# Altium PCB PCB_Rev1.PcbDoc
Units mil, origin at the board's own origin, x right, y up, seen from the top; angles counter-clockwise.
Board outline 802 x 1535 mil, 4 copper layers (Top Layer, Signal Layer 1, Internal Plane 1(GND), Bottom Layer), stack 30.634 mil thick; 54 components, 46 nets, 254 pads, 102 vias.
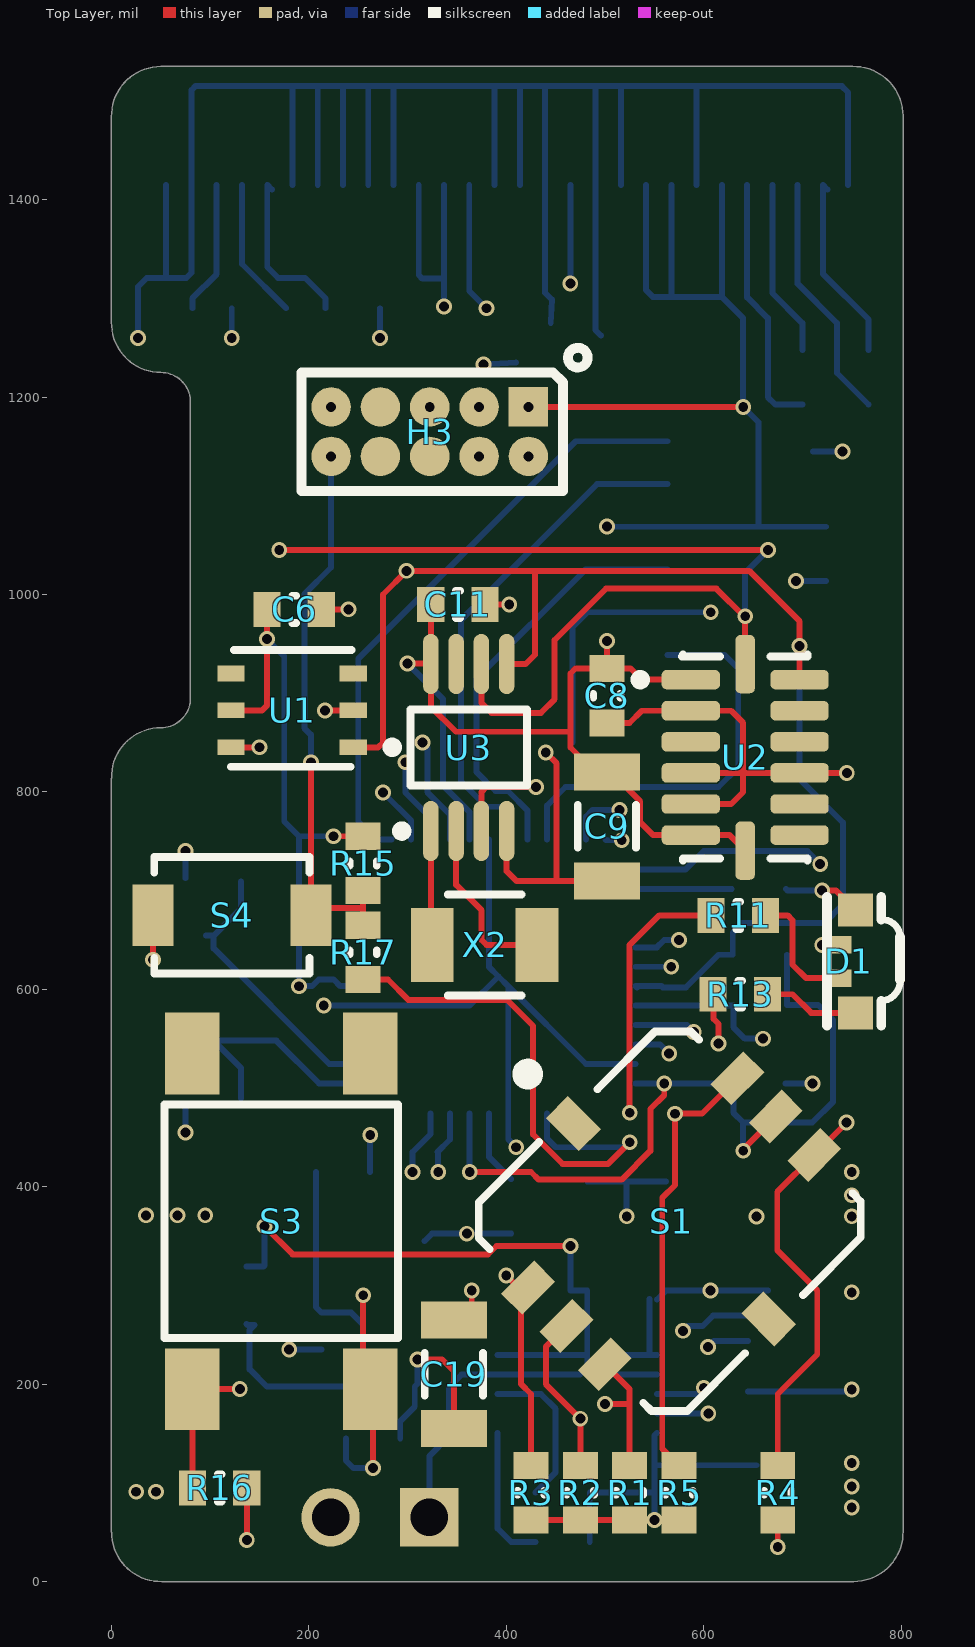
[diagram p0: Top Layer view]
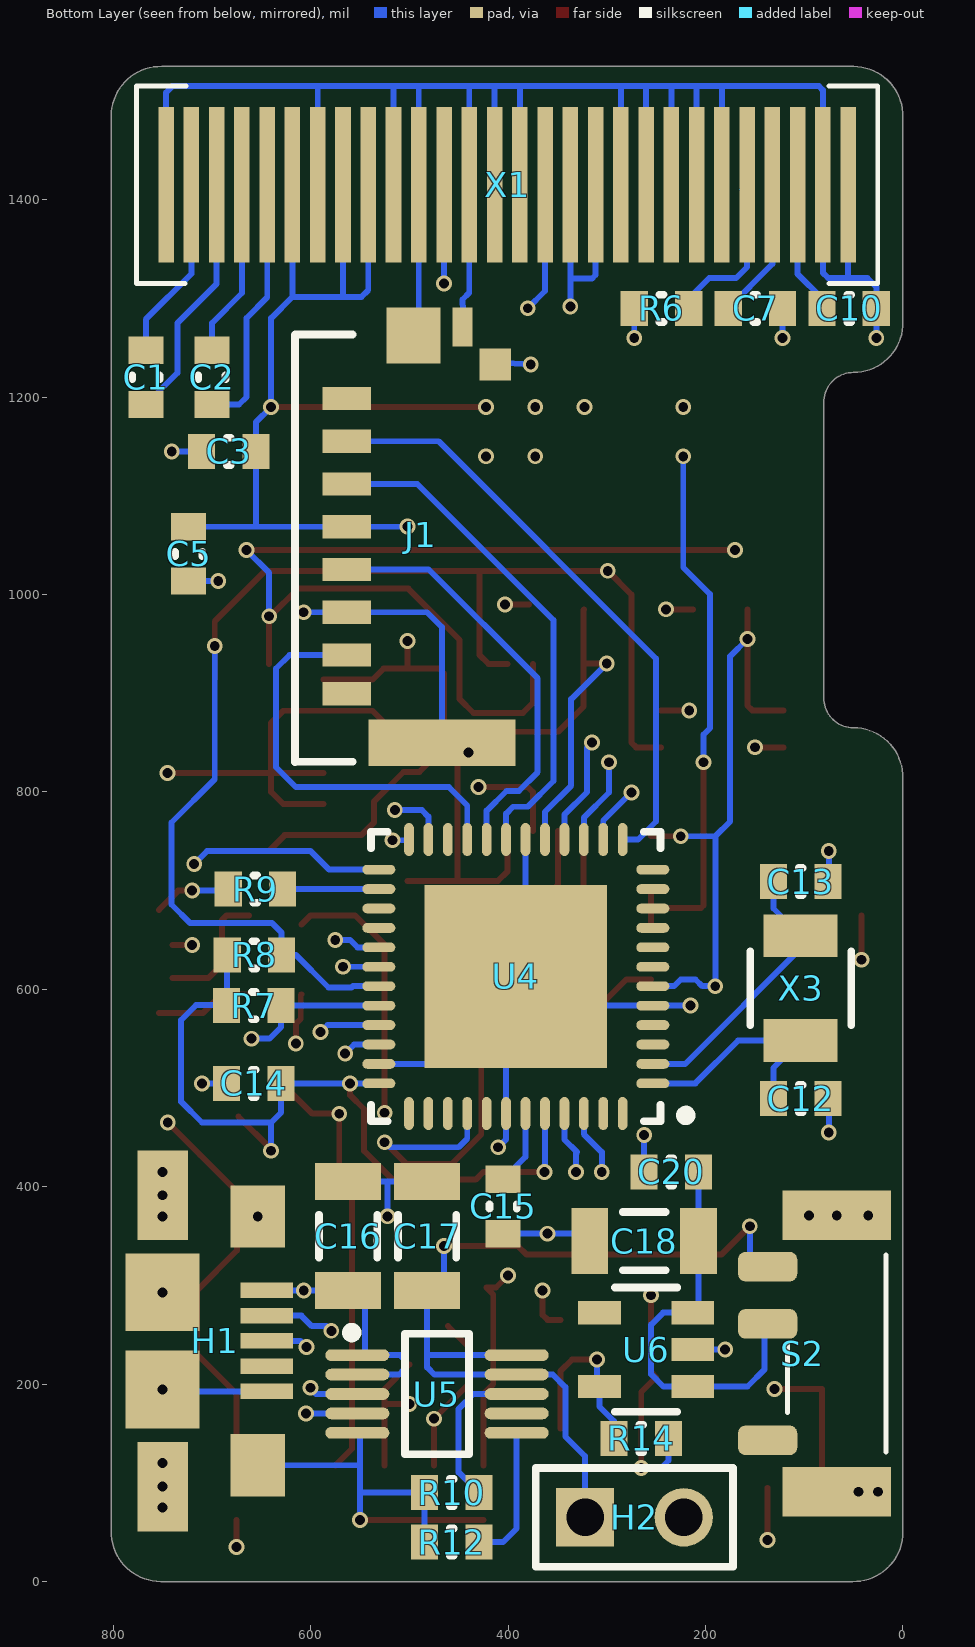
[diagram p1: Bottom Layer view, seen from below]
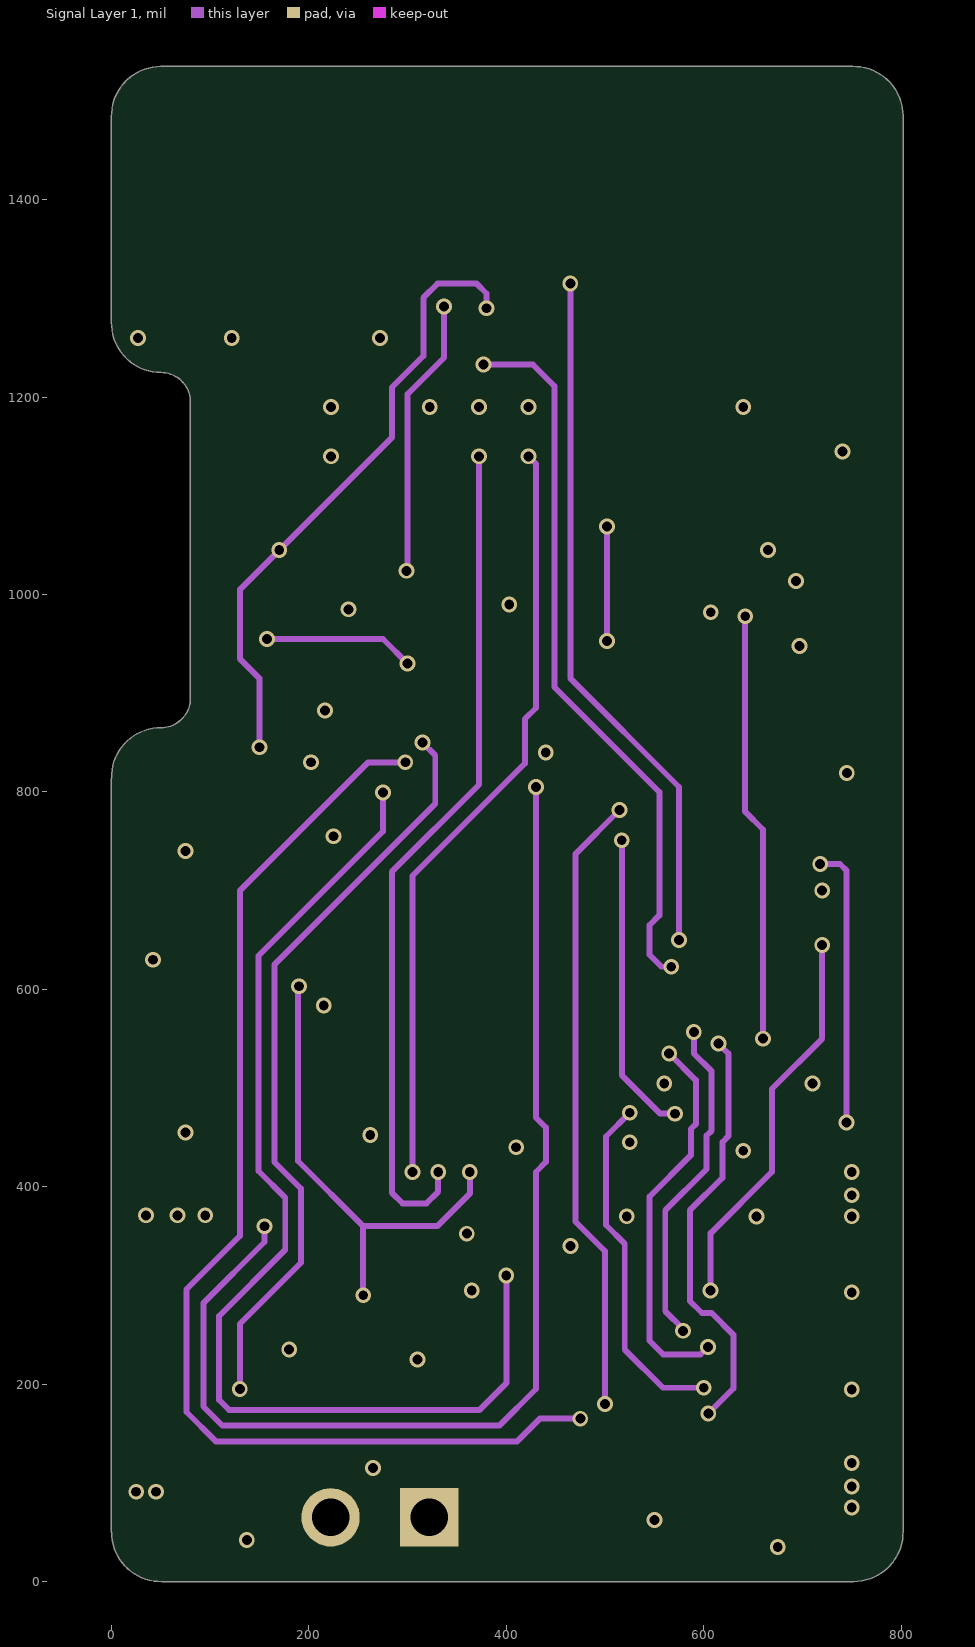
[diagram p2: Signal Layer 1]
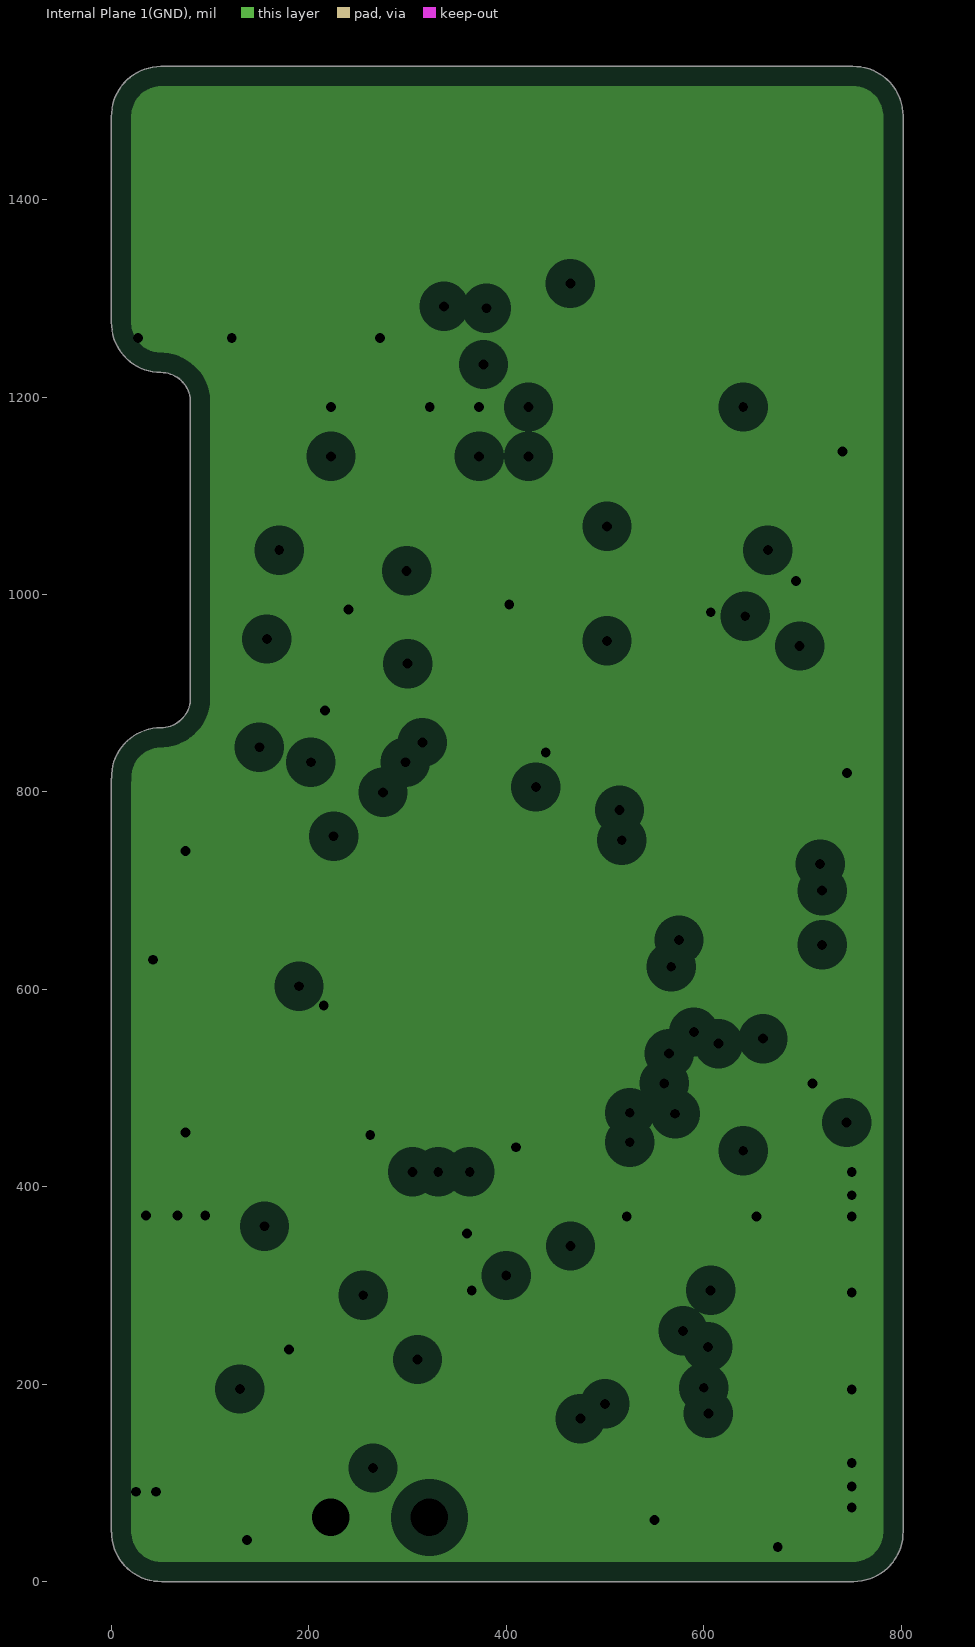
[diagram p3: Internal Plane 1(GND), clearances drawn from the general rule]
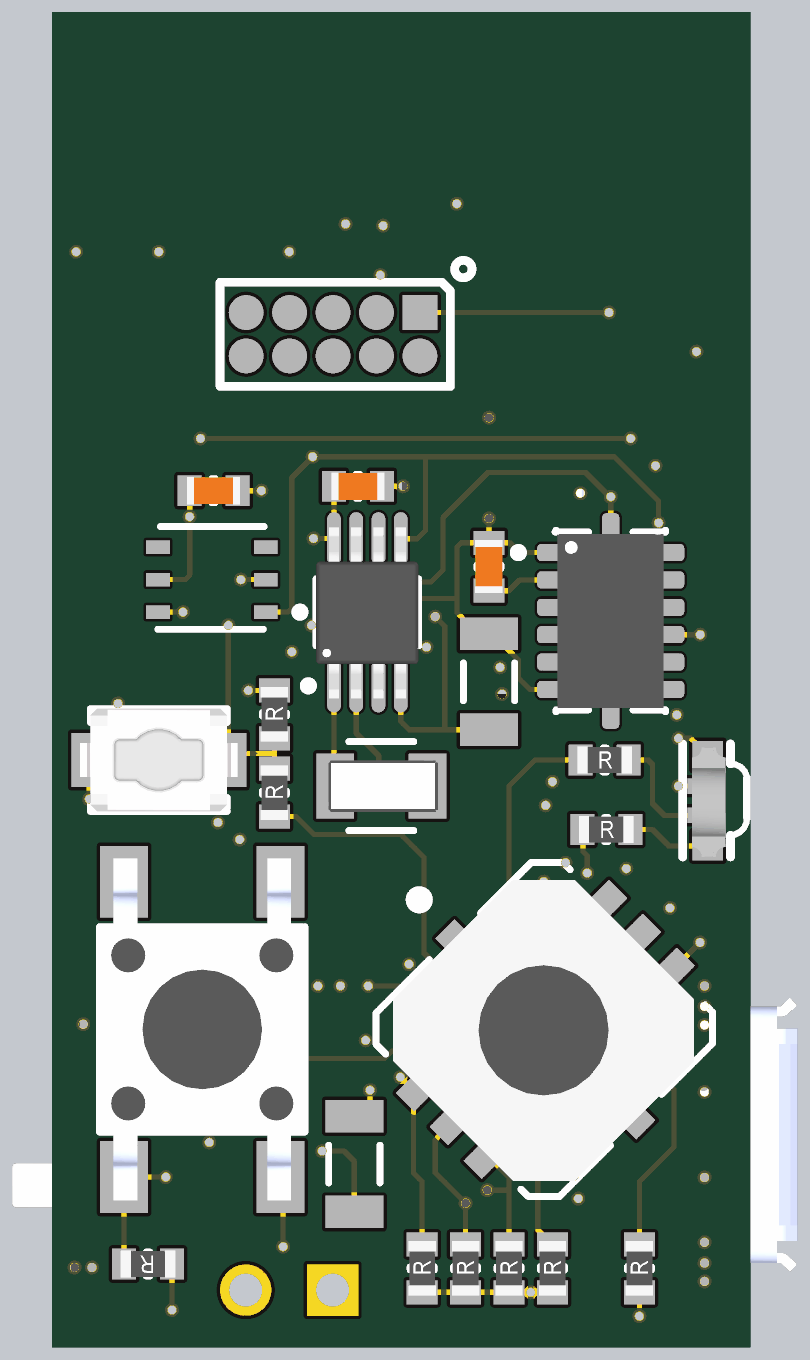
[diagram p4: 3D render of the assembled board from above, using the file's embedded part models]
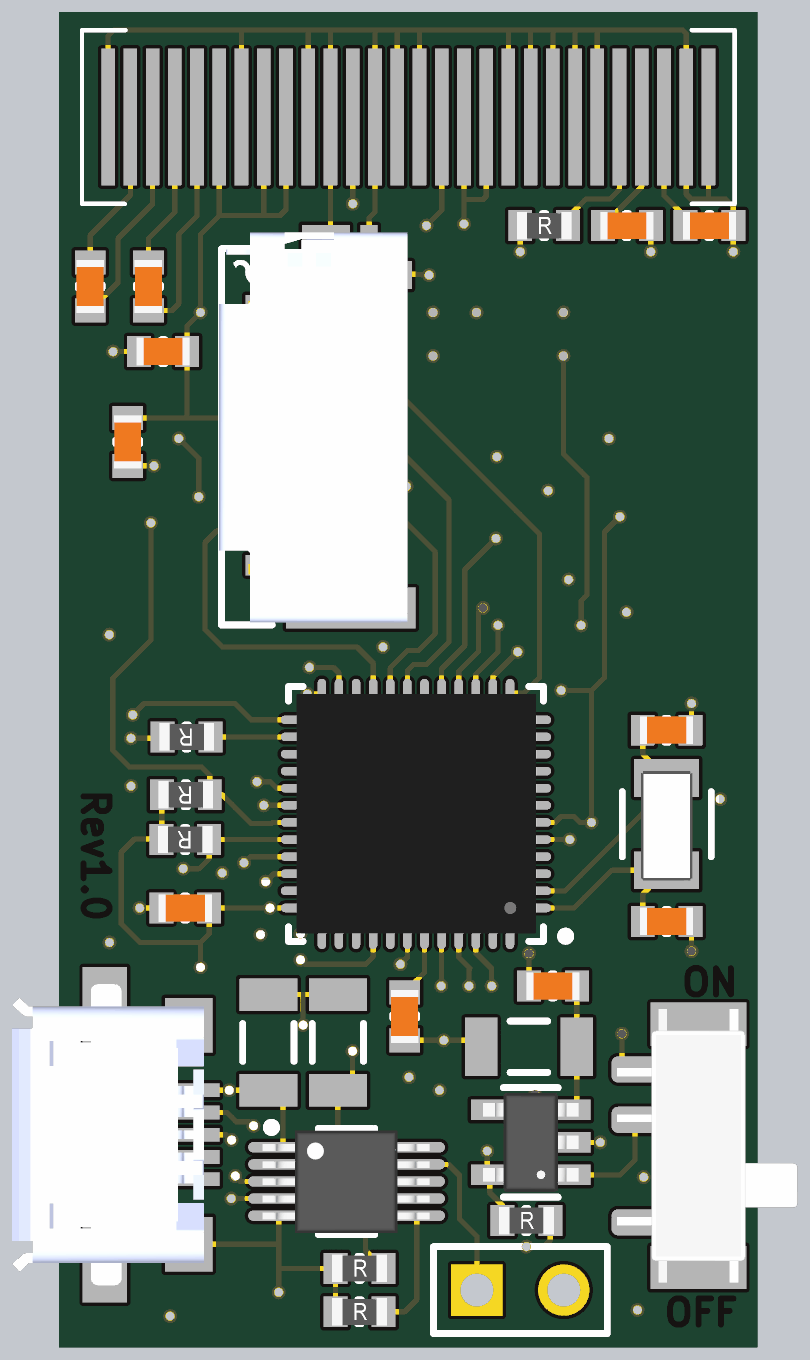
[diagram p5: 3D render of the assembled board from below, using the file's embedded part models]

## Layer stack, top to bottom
Top Solder: solder mask 0.4, Solder Resist, Dk 3.5
Top Layer: signal copper 1.4
Dielectric 1: core 10, FR-4, Dk 4.2
Signal Layer 1: signal copper 1.417
Dielectric 4: prepreg 5, Dk 4.2
Internal Plane 1(GND): plane copper 1.417, net GND
Dielectric 3: core 10, Dk 4.2
Bottom Layer: signal copper 1.4
Bottom Solder: solder mask 0.4, Solder Resist, Dk 3.5

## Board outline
-0.03,49.99 -0.03,814.03 0.01,814.03 cw(c50,815) 50,865 ccw(c50,895) 79.99,895.58 80,895.58 80,1194.42 79.99,1194.42 ccw(c50,1195) 50,1225 49.96,1225.03 cw(c49.96,1275.03) -0.03,1276 -0.03,1484 cw(c49.96,1484.97) 49.96,1534.97 49.96,1535 750.97,1535 cw(c751.94,1485.01) 801.94,1485.01 801.97,1485.01 801.97,51 cw(c751.98,50.03) 751.98,0.03 751.98,0 50.97,0 cw(c50,49.99)

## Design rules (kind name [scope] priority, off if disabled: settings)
Clearance Clearance_J1 [All vs HasFootprint ('0473092851')] p1: gap=7.5
Clearance Clearance_D1 [All vs HasFootprint ('HSMF-C115')] p2: gap=9.5
Clearance Clearance_U5 [All vs HasFootprint ('TSSOP50P490X110-10N')] p3: gap=7.8
Clearance Clearance_H1 [All vs HasFootprint ('1981584-1')] p4: gap=9.5
Clearance Clearance_U3 [All vs HasFootprint ('TSOP65P490X110-8N')] p5: gap=9.5
Clearance Clearance_U4 [HasFootprint ('QFN48')] p6: gap=9.5
Clearance Clearance_X1 [HasFootprint ('OLED_GLASS 0.66 INCH')] p7: gap=9.5
Clearance [All] p8: gap=10
MinimumSolderMaskSliver [All] p1: minsoldermaskwidth=2
PlaneClearance [All] p1: clearance=20
PlaneConnect PlaneConnect_Via [(IsVia)] p1: planeconnectstyle=Direct reliefexpansion=20 reliefentries=4 reliefconductorwidth=10 reliefairgap=10
PlaneConnect [All] p2: planeconnectstyle=Relief reliefexpansion=20 reliefentries=4 reliefconductorwidth=10 reliefairgap=10
PolygonConnect [All] p1: connectstyle=Relief reliefconductorwidth=10 reliefentries=4 polygonreliefangle="90 Angle" airgapwidth=10
RoutingVias [All] p1: holewidth=10 width=16 viastyle="Through Hole" minholewidth=10 minwidth=16 maxholewidth=20 maxwidth=50
SilkToSilkClearance [All] p1: silktosilkclearance=5
SilkToSolderMaskClearance [IsPad] p1: minsilkscreentomaskgap=3 clearancetoexposedcopper=TRUE
SolderMaskExpansion [All] p1: expansion=4
Width [All] p1: maxlimit=10 minlimit=6 preferedwidth=6
25 further rules are at their usual default settings.

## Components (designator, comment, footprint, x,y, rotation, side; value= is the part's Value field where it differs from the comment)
C1 "1uF" CAPC1608X09L 767,1220 r90 bottom
C2 "1uF" CAPC1608X09L 700,1220 r90 bottom
C3 "1uF" CAPC1608X09L 683,1145 r180 bottom
C5 "0.1uF" CAPC1608X09L 723.68,1041.12 r90 bottom
C6 "0.1uF" CAPC1608X09L 185,985 r180 top
C7 "4.7uF" CAPC1608X09L 149.41,1290 r0 bottom
C8 "0.1uF" CAPC1608X09L 501.97,897.44 r90 top
C9 "10uF" CAPC3216X160L 501.97,765 r270 top
C10 "2.2uF" CAPC1608X09L 54.41,1290 r0 bottom
C11 "0.1uF" CAPC1608X09L 351,990 r180 top
C12 "22pF" CAPC1608X09L 103.52,489.22 r180 bottom
C13 "22pF" CAPC1608X09L 103.52,709.22 r180 bottom
C14 "0.1uF" CAPC1608X09L 657.56,504.73 r0 bottom
C15 "1uF" CAPC1608X09L 405,380 r90 bottom
C16 "4.7uF" CAPC3216X160L 561.97,350 r90 bottom
C17 "4.7uF" CAPC3216X160L 481.97,350 r90 bottom
C18 "4.7uF" CAPC3216X160L 262.09,345 r0 bottom
C19 "4.7uF" CAPC3216X160L 346.97,210 r90 top
C20 "0.1uF" CAPC1608X09L 234.53,415 r0 bottom
D1 "RGB" HSMF-C115 753.78,680.45 r270 top
H1 "Micro USB" 1981584-1 697.31,243.79 r270 bottom
H2 "CON2" HDR1X2-EMPTY 271.97,65 r180 bottom
H3 "CON5X2-50MIL" HDR5X2-50MIL-SMT 322.44,1165 r180 top
J1 "0473092851" 0473092851 563.49,1047.03 r90 bottom locked
R1 "10K" RESC1608X06L 525,90 r90 top
R2 "10K" RESC1608X06L 475,90 r90 top
R3 "10K" RESC1608X06L 425,90 r90 top
R4 "10K" RESC1608X06L 675,90 r90 top
R5 "10K" RESC1608X06L 575,90 r90 top
R6 "390K" RESC1608X06L 244.53,1290 r180 bottom
R7 "10K" RESC1608X06L 657.56,583.47 r0 bottom
R8 "10K" RESC1608X06L 656.97,635 r0 bottom
R9 "470R" RESC1608X06L 655.98,701.58 r0 bottom
R10 "10K" RESC1608X06L 456.97,90 r180 bottom
R11 "470R" RESC1608X06L 635,675 r0 top
R12 "1K" RESC1608X06L 457,40 r180 bottom
R13 "470R" RESC1608X06L 636.97,595 r0 top
R14 "0R" RESC1608X06L 265,145 r180 bottom
R15 "10K" RESC1608X06L 255,727.56 r90 top
R16 "10K" RESC1608X06L 109.56,95 r180 top
R17 "330R" RESC1608X06L 255,637.44 r90 top
S1 "Navigation Switch" "NAVIGATION - DX" 566.97,365 r0 top
S2 "" SLIDE_SWITCH_DX 66.97,231 r90 bottom
S3 "Tactile_Switch" FSM6JSMA 171.97,365 r180 top
S4 "Push" TL1015AF160QG 121.97,675 r0 top
U1 "HDC1080DMBT" S-PWSON-N6 245,845.2 r180 top
U2 "ADXL345BCCZ-RL7" LGA80P300X500X100-14N 641.97,835 r0 top
U3 "DS1340U-33+" TSOP65P490X110-8N 361.97,845 r90 top
U4 "ATSAMD21G18A-MU" QFN48 392.11,613 r0 bottom
U5 "MCP73833-FCI/UN" TSSOP50P490X110-10N 471.97,190 r180 bottom
U6 "LP2985-33DBVR" SOT95P280X144-5N 260,235 r0 bottom
X1 "OLED_GLASS 0.66 inch" "OLED_GLASS 0.66 INCH" 400.87,1415 r180 top
X2 "ECS-.327-12.5-34B" ECS-.327-12.5-34B 380,645 r180 top
X3 "ECS-.327-12.5-34B" ECS-.327-12.5-34B 103.52,599.22 r90 bottom

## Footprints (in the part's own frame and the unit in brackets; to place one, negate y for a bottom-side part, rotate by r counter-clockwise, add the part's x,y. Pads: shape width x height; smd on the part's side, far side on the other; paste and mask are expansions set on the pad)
1981584-1 [mm] "CONN RCPT MICRO USB TYPE AB"
  rect 0.4x1.35 smd: 1(-1.3,1.338) 2(-0.65,1.338) 3(0,1.338) 4(0.65,1.338) 5(1.3,1.338)
  rect 2.3x1.3 smd: 6(-3.75,-1.337) 6(3.75,-1.337)
  rect 1.6x1.4 smd: 6(-3.2,1.113) 6(3.2,1.113)
  rect 2x1.9 smd: 6(-1.25,-1.337) 6(1.25,-1.337)
  body extent -4.4,-4.05 4.4,1.55, height 2.75
0473092851 [mm] "CONN MICRO SD CARD PUSH-PULL R/A"
  rect 0.6x1.25 smd: 1(3.85,0) 2(2.75,0) 3(1.65,0) 4(0.55,0) 5(-0.55,0) 6(-1.65,0) 7(-2.75,0) 8(-3.75,0)
  rect 1.2x3.79 smd: G1(-5.004,-2.451)
  rect 1.45x1.4 smd: G2(5.472,-1.719)
  rect 1x0.508 smd: G3(5.687,-2.982)
  rect 0.813x0.813 smd: G4(4.725,-3.825)
  silkscreen extent -5.51,-0.15 5.5,1.33, body extent -5.43,-4.1 5.97,1.4, height 2.88
CAPC1608X09L [mm] "Chip Capacitor, 2-Leads, Body 1.6x0.8mm, IPC High Density (0603 dense)"
  rect 0.7x0.9 smd: 1(-0.7,0) 2(0.7,0)
  silkscreen extent -0.05,-0.35 0.05,0.35, body extent -0.89,-0.48 0.88,0.48, height 1.03
CAPC3216X160L [mm] "Chip Capacitor, 2-Leads, Body 3.2x1.6mm, IPC Least Density(C1206)"
  rect 0.95x1.7 smd: 1(-1.4,0) 2(1.4,0)
  silkscreen extent -0.55,-0.75 0.55,0.75, body extent -1.7,-0.9 1.7,0.9, height 1.9
ECS-.327-12.5-34B [mm] "SMT Crystal, 2-Leads, Body 3.2x1.5mm, IPC Medium Density"
  rect 1.1x1.9 smd: 1(-1.3,0) 2(1.4,0)
  silkscreen extent -0.9,-1.3 1,1.3, body extent -1.6,-0.75 1.6,0.75, height 0.91
FSM6JSMA [mil] "SWITCH TACTILE SPST-NO 0.05A 12V"
  rect 55.12x82.68 smd: 1(90,170) 2(90,-170) 3(-90,170) 4(-90,-170)
  silkscreen extent -118,-118 118,118, body extent -118,-197 118,197, height 276
HDR1X2-EMPTY [mm]
  rect 1.5x1.5 hole 0.965: 1(-1.27,0)
  round 1.5 hole 0.965: 2(1.27,0)
  silkscreen extent -2.54,-1.27 2.54,1.27
HDR5X2-50MIL-SMT [mil]
  rect 40x40 smd: 1(-100,-25)
  round 40 smd: 2(-100,25) 3(-50,-25) 4(-50,25) 5(0,-25) 6(0,25) 7(50,-25) 8(50,25) 9(100,-25) 10(100,25)
  silkscreen extent -160,-85 130,60
HSMF-C115 [mm] "Led RGB 10mA SMD R/A RoHS"
  rect 0.85x0.9 smd: 1(0,0) 4(2.65,0)
  rect 0.45x0.5 smd: 2(0.9,-0.35) 3(1.757,-0.35)
  silkscreen extent -0.33,-0.74 2.97,1.15, body extent -0.23,-0.47 2.97,0.52, height 1.4
LGA80P300X500X100-14N [mm] "LGA, 14-Pins, Body 3.2x5.2mm (max), Pitch 0.80mm, IPC Medium Density"
  rrect50% 1.5x0.5 smd mask+0.076: 1(-1.399,2) 2(-1.399,1.2) 3(-1.399,0.4) 4(-1.399,-0.4) 5(-1.399,-1.2) 6(-1.399,-2) 8(1.401,-2) 9(1.401,-1.2) 10(1.401,-0.4) 11(1.401,0.4) 12(1.401,1.2) 13(1.401,2)
  rrect50% 0.5x1.5 smd mask+0.076: 7(0.001,-2.4) 14(0.001,2.4)
  silkscreen extent -2.82,-2.65 1.6,2.65, body extent -1.55,-2.55 1.55,2.55, height 1
"NAVIGATION - DX" [mm] "Navigation Switch - DX"
  rect 1.2x0.762 smd rot 45: 1(-3.682,-1.706) 2(-2.694,-2.694) 3(-1.706,-3.682) 4(3.682,1.706) 5(2.694,2.694) 6(1.706,3.682)
  rect 0.8x1.2 smd rot 45: ""(-2.514,2.514) ""(2.514,-2.514)
  silkscreen extent -4.95,-4.88 4.88,4.88, body extent -5.35,-5.33 5.24,5.27, height 4.32
"OLED_GLASS 0.66 INCH" [mm] "OLED_GLASS 0.66 INCH"
  rect 0.4x4 smd far side: 1(-8.775,0) 2(-8.125,0) 3(-7.475,0) 4(-6.825,0) 5(-6.175,0) 6(-5.525,0) 7(-4.875,0) 8(-4.225,0) 9(-3.575,0) 10(-2.925,0) 11(-2.275,0) 12(-1.625,0) 13(-0.975,0) 14(-0.325,0) 15(0.325,0) 16(0.975,0) 17(1.625,0) 18(2.275,0) 19(2.925,0) 20(3.575,0) 21(4.225,0) 22(4.875,0) 23(5.525,0) 24(6.175,0) 25(6.825,0) 26(7.475,0) 27(8.125,0) 28(8.775,0)
QFN48 [mm] "QFN, 48-Leads, Body 7x7mm, Pitch 0.5mm, IPC Medium Density"
  oval 0.85x0.25 smd: 1(-3.525,2.75) 2(-3.525,2.25) 3(-3.525,1.75) 4(-3.525,1.25) 5(-3.525,0.75) 6(-3.525,0.25) 7(-3.525,-0.25) 8(-3.525,-0.75) 9(-3.525,-1.25) 10(-3.525,-1.75) 11(-3.525,-2.25) 12(-3.525,-2.75) 25(3.525,-2.75) 26(3.525,-2.25) 27(3.525,-1.75) 28(3.525,-1.25) 29(3.525,-0.75) 30(3.525,-0.25) 31(3.525,0.25) 32(3.525,0.75) 33(3.525,1.25) 34(3.525,1.75) 35(3.525,2.25) 36(3.525,2.75)
  oval 0.25x0.85 smd: 13(-2.75,-3.525) 14(-2.25,-3.525) 15(-1.75,-3.525) 16(-1.25,-3.525) 17(-0.75,-3.525) 18(-0.25,-3.525) 19(0.25,-3.525) 20(0.75,-3.525) 21(1.25,-3.525) 22(1.75,-3.525) 23(2.25,-3.525) 24(2.75,-3.525) 37(2.75,3.525) 38(2.25,3.525) 39(1.75,3.525) 40(1.25,3.525) 41(0.75,3.525) 42(0.25,3.525) 43(-0.25,3.525) 44(-0.75,3.525) 45(-1.25,3.525) 46(-1.75,3.525) 47(-2.25,3.525) 48(-2.75,3.525)
  rect 4.7x4.7 smd paste-0.5: 49(0,0)
  silkscreen extent -4.5,-3.72 3.72,3.72, body extent -3.52,-3.51 3.5,3.51, height 0.78
RESC1608X06L [mm] "Chip Resistor, 2-Leads, Body 1.6x0.8mm, IPC High Density (0603 dense)"
  rect 0.7x0.9 smd: 1(-0.7,0) 2(0.7,0)
  silkscreen extent -0.05,-0.35 0.05,0.35, body extent -0.85,-0.47 0.85,0.47, height 0.6
S-PWSON-N6 [mm] "DMB (S-PWSON-N6)"
  rect 0.7x0.4 smd mask+0.076: 1(0,0) 2(0,-0.95) 3(0,-1.9) 5(3.15,-0.95) 6(3.15,0)
  rect 0.7x0.4 smd paste+0 mask+0.076: 4(3.15,-1.9)
  silkscreen extent -1.13,-2.5 3.15,0.5, body extent 0,-2.57 3.15,0.58, height 0.8
SLIDE_SWITCH_DX [mil] "Slide Switch DX"
  rrect50% 30x60 smd: 1(88,70) 2(30,70) 3(-88,70)
  rect 50x110 smd: 4(-140,0) 5(140,0)
  silkscreen extent -100,-50 100,50, body extent -157,-114 158,94, height 60
SOT95P280X144-5N [mm] "SOT23, 5-Leads, Body 3.1x3.0mm (max), Pitch 0.95mm, IPC Medium Density (RFMD SOT23-5)"
  rect 1.1x0.6 smd: 1(-1.2,0.95) 2(-1.2,0) 3(-1.2,-0.95) 4(1.2,-0.95) 5(1.2,0.95)
  silkscreen extent -0.8,-1.6 0.8,1.6, body extent -1.4,-1.45 1.4,1.45, height 1.45
TL1015AF160QG [mm] "SWITCH TACTILE SPST-NO 0.05A 12V"
  rect 1.05x1.59 smd: 1(-2.032,0) 2(2.032,0)
  silkscreen extent -2,-1.5 2,1.5, body extent -2.3,-1.5 2.3,1.5, height 2
TSOP65P490X110-8N [mm] "TSOP, 8-Leads, Body 3.0x3.0mm (max), Pitch 0.65mm, IPC Medium Density"
  oval 1.55x0.4 smd mask+0.076: 1(-2.15,0.975) 2(-2.15,0.325) 3(-2.15,-0.325) 4(-2.15,-0.975) 5(2.15,-0.975) 6(2.15,-0.325) 7(2.15,0.325) 8(2.15,0.975)
  silkscreen extent -2.27,-1.5 0.97,1.85, body extent -2.51,-1.5 2.49,1.5, height 1.1
TSSOP50P490X110-10N [mm] "TSSOP, 10-Leads, Body 3.1x3.1mm (max), Pitch 0.50mm, IPC Medium Density(10MSOP)"
  oval 1.65x0.3 smd: 1(-2.05,1) 2(-2.05,0.5) 3(-2.05,0) 4(-2.05,-0.5) 5(-2.05,-1) 6(2.05,-1) 7(2.05,-0.5) 8(2.05,0) 9(2.05,0.5) 10(2.05,1)
  silkscreen extent -2.32,-1.55 0.82,1.7, body extent -2.45,-1.51 2.43,1.49, height 1.04

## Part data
C1 C2 C3 C15: library part CAP_0603, "CAP, 1uF, 0603"
C5 C6 C8 C11 C14 C20: library part CAP_0603, "CAP, 0.1uF, 0603"
C7: library part CAP_0603, "CAP, 4.7uF, 0603"
C9: library part CAP_1206, "CAP, 40uF, 1206"
C10: library part CAP_0603, "CAP, 2.2uF, 0603"
C12 C13: library part CAP_0603, "CAP, 22pF, 0603"
C16 C17 C18 C19: library part CAP_1206, "CAP, 4.7uF, 1206"
D1: library part HSMF-C115, "LED,RGB,10mA,SMD,R/A,RoHS"
H1: library part 1981584-1, "CONN RCPT MICRO USB TYPE AB"
H2: library part CON2-EMPTY_PAD, "EMPTY SOLDER 2POS"
H3: library part CON5X2_50mil, "JTAG CONN HEADER 5X2POS 50mil\" PADS"
J1: "9 (8 + 1) microSD SMT, Right Angle"
R1 R2 R3 R4 R5 R10 R15 R16: library part RES_0603, "RES, 10K, 0603"
R6: library part RES_0603, "RES, 390K, 0603"
R7 R8 R11 R12 R13: library part RES_0603, "RES, 470R, 0603"
R9: library part RES_0603, "RES,470R, 0603"
R14: library part RES_0603, "RES, 0R, 0603"
R17: library part RES_0603, "RES, 330R, 0603"
S1: library part DX_NAV, "DX_Navigation Switch"
S2: library part DX_SLIDE_SWITCH, "DX_SWITCH SLIDE SPDT R/A"
S3: library part FSM6JSMA, "SWITCH TACTILE SPST-NO 0.05A 12V"
S4: library part DX_MINI_TACT_SWITCH, "DX_SWITCH TACTILE"
U1: "Humidity/Temperature Sensor"
U2: "IC ACCEL SPI/I2C 3AX 14LGA"
U3: "IC RTC SERIAL 512K 8-TSSOP"
U4: "IC MCU 32BIT 256KB FLASH 48QFN"
U5: "IC LI-ION/LI-POLY CTRLR 10MSOP"
U6: "IC REG LDO 3.3V .15A SOT23-5"
X1: "0.66 inch OLED_GLASS_Blue"
X2 X3: "CRYSTAL 32.768 KHZ 12.5PF SMD"

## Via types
v1: diameter 16, hole 10, Top Layer to Bottom Layer, tented both sides, 102 vias

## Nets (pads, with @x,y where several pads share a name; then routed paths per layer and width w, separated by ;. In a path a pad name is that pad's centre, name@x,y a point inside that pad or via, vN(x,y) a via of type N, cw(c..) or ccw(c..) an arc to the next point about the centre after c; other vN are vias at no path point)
3.6V_LIPO: C17.1 H2.1 S2.1 U3.3 U5.9 U5.10 | length 2187
  Top Layer w6: v1(155,360) 183.56,331.44 381.44,331.44 390,340 v1(465,340) ; U3.3 374.77,799.77 380,805 v1(430,805)
  Signal Layer 1 w6: v1(155,360) 155,344 93,282 93,177.37 112.37,158 393,158 430,195 430,415 440,425 440,460 430,470 v1(430,805)
  Bottom Layer w6: S2.1 154,319 155,320 v1(155,360) ; H2.1 321.97,126.97 341.9,146.9 341.9,196.9 354.69,209.69 U5.9 474.69,209.69 481.97,216.97 481.97,230 ; U5.10 481.34,229.37 481.97,230 ; v1(465,340) 465,295 465.12,294.88 C17.1 481.97,230
+3.3V: C3.2 C5.2 C6.2 C8.2 C9.1 C11.2 C14.1 H3.1 J1.4 R7.2 R8.2 R14.2 R15.2 S1.5 S3.3 U1.5 U2.1 U2.6 U2.7 U3.8 U4.6 U4.17 U4.36 U4.44 X1.6 X1.8 X1.9 | length 4510.7
  Top Layer w6: U1.5 152.6,882.6 157.44,887.44 v1(157.44,955) C6.2 ; v1(225,755.12) R15.2 ; v1(255,290) 255,211.97 250,206.97 S3.3 265,191.97 v1(265,115) ; v1(300,930) 323.23,930 U3.8 ; C11.2@323,985 323.59,984.41 U3.8 ; v1(363,415) 425,415 432.84,407.16 516.85,407.16 546,436.3 546,444.44 546,478.7 560,492.7 v1(560,504.73) ; v1(422.44,1190) v1(640,1190) ; v1(501.97,953.03) C8.2 ; U2.1 537.26,913.74 526,925 C8.2 ; v1@638.49,436.51 v1(640,436.51) 640,438.03 S1.5 ; U2.7 626.27,756.26 U2.6 548.74,756.26 535.69,769.31 535.69,790.39 505.96,820.12 C9.1 489.88,820.12 465,845 465,861 ; U3.8 323.59,886.41 349,861 465,861 ; 465,861 465,920 470,925 C8.2
  Signal Layer 1 w6: v1(157.44,955) 275,955 v1(300,930) ; v1@190,605 v1(190,603.16) 189,602.16 189,426 255,360 ; v1(255,290) 255,360 ; v1(363,415) 363,393 330,360 255,360 ; v1(501.97,953.03) v1(501.97,1069)
  Bottom Layer w6: v1(157.44,955) 175,937.44 175,770 190,755 ; v1(225,755.12) 190.12,755.12 190,755 ; R14.2 237.44,122.56 245,115 v1(265,115) ; U4.6 231.84,603.16 225,610 210,610 203.16,603.16 v1(190,603.16) 190,755 ; v1(300,930) 336,894 336,806.37 362.58,779.79 U4.17 ; v1@362.58,415 U4.44 ; v1@502,1068.68 J1.4 655,1068.68 ; U4.36 v1(560,504.73) C14.1 630,475 640,465 ; X1.9 541.62,1308.38 548.39,1301.61 568.39,1301.61 ; X1.8 567.21,1302.79 568.39,1301.61 ; X1.6 618.39,1301.61 ; v1(640,436.51) 640,465 ; R8.2 684.53,584.06 715.94,584.06 731.12,568.88 731.12,486.12 710,465 640,465 ; C5.2 655,1068.68 ; 568.39,1301.61 618.39,1301.61 ; 618.39,1301.61 640,1280 v1(640,1190) 655.44,1174.56 C3.2 655.44,1069.12 655,1068.68
D13: D1.1 R9.2 | length 79
  Top Layer w6: v1(720,700) 734.23,700 D1.1
  Bottom Layer w6: R9.2 685.12,700 v1(720,700)
D+: H1.3 U4.34 | length 470.7
  Signal Layer 1 w6: v1(565,535) 592,508 592,463.47 587,458.47 587,432 545,390 545,244 559,230 596.56,230 v1(604.26,237.71)
  Bottom Layer w6: U4.34 555.9,544.1 v1(565,535) ; v1(604.26,237.71) 610.34,243.79 H1.3
D-: H1.2 U4.33 | length 471.2
  Signal Layer 1 w6: v1(579,254) 579,256 561,274 561,376 603,418 603,451.84 608,456.84 608,517 590,535 v1(590,556.77)
  Bottom Layer w6: U4.33 582.98,563.79 v1(590,556.77) ; v1(579,254) 583.71,258.71 598.71,258.71 609.38,269.38 H1.2
GND: C3.1 C5.1 C6.1 C7.1 C8.1 C9.2 C10.1 C11.1 C12.2 C13.2 C14.2 C15.1 C16.2 C17.2 C18.2 C19.2 C20.2 H1.5 H1.6 H2.2 H3.3 H3.5 H3.9 J1.6 J1.G1 J1.G2 J1.G3 R1.1 R2.1 R3.1 R4.1 R5.1 R6.1 R10.1 R12.1 R16.1 S2.4 S2.5 S4.1 U1.2 U2.2 U2.4 U2.5 U2.10 U3.4 U4.5 U4.18 U4.35 U4.42 U4.49 U5.5 U6.2 X1.1 X1.7 X1.10 X1.11 X1.13 X1.14 X1.15 X1.19 X1.20 X1.21 X1.22 X1.23 X1.27 X1.28 | length 5473.1
  Top Layer w6: v1(41.97,630) S4.1 ; v1(137.12,42.12) R16.1 ; C6.1 v1(240,985) ; v1(216.41,882.6) U1.2 ; C19.2 359.88,265.12 365,270.24 v1(365,295) ; C11.1 v1(403,990) ; U3.4 400.36,719.64 410.12,709.88 451,709.88 ; R3.1 R2.1 R1.1 v1(550,62.44) ; v1@441,839 451,829 451,709.88 ; C9.2 451,709.88 ; C8.1 524.88,869.88 537.24,882.24 U2.2 627.76,882.24 640,870 640,819.25 ; U2.5 627.76,787.76 640,800 640,819.25 ; U2.4 640,819.25 ; v1(675,35) R4.1 ; v1(745,819.25) U2.10 640,819.25
  Bottom Layer w6: v1(26.85,1259.88) C10.1 26.85,1311.85 35.72,1320.72 55,1320.72 ; X1.28 55.4,1321.11 55,1320.72 ; v1(75,455) C12.2@75,482.44 ; C13.2@75,712.56 v1(75,740) ; v1(121.85,1259.88) C7.1 ; v1(180,235) U6.2 ; X1.23 183.35,1515 ; X1.22 208.94,1515 ; v1(215,583.47) U4.5 362.58,583.47 U4.49 ; X1.21 234.53,1515 ; X1.20 260.12,1515 ; C20.2 v1(262.09,452.39) ; v1(272.09,1259.88) R6.1 ; X1.19 285.71,1515 ; C18.2 324.65,352.44 v1(360,352.44) C15.1 ; U4.18 382.26,622.84 U4.49 ; X1.15 388.07,1515 ; v1(410,440) 401.95,448.05 U4.42 U4.49@401.95,603.16 ; X1.14 413.67,1515 ; J1.G3@445,1275 446.09,1298.91 439.26,1305.74 X1.13 439.26,1515 ; J1.G1 466.97,966.97 482.07,982.07 J1.6 v1(607.07,982.07) ; C17.2 521.97,405.12 ; R10.1 549.88,90 550,90.12 ; R12.1 R10.1 ; J1.G2 490.44,1267.8 X1.11 490.44,1515 ; X1.10 516.03,1515 ; v1(521.97,370) 521.97,405.12 ; U4.35 480.69,524.42 U4.49@401.95,603.16 ; v1(550,62.44) 550,90.12 ; U5.5 550,147.95 550,117.8 ; C16.2 521.97,405.12 ; X1.7 592.8,1515 ; H1.5 748,192.61 v1(749.97,194.57) ; H1.6@653.52,117.8 550,117.8 ; C14.2@682.68,504.73 C14.2 v1(710.12,504.73) ; v1(693.56,1013.56) C5.1 ; C3.1 v1(740.68,1145) ; X1.1 746.34,1508.66 740,1515 592.8,1515 ; 55,1320.72 75.72,1320.72 80.99,1325.99 X1.27 80.99,1510.99 85,1515 183.35,1515 ; 183.35,1515 208.94,1515 ; 208.94,1515 234.53,1515 ; 234.53,1515 260.12,1515 ; 260.12,1515 285.71,1515 ; 285.71,1515 388.07,1515 ; 388.07,1515 413.67,1515 ; U4.49 U4.49@401.95,603.16 ; 413.67,1515 439.26,1515 ; 439.26,1515 490.44,1515 ; 490.44,1515 516.03,1515 ; 516.03,1515 592.8,1515 ; 550,90.12 550,117.8
  other v1: 750,75 25,91 45,91 749.97,96.15 750,120 749.97,293 653.52,369.77 750,370 35,371 66.97,371 95,371 749.97,391.43 750,415 440,840 222.44,1190 322.44,1190 372.44,1190
NetC1_1: C1.1 X1.3 | length 252.3
  Bottom Layer w6: X1.3 695.16,1314.84 735,1275 735,1224.44 C1.1
NetC1_2: C1.2 X1.2 | length 193.3
  Bottom Layer w6: X1.2@725.47,1410.28 X1.2 720.75,1325 767,1278.75 C1.2
NetC2_1: C2.1 X1.5 | length 261.8
  Bottom Layer w6: X1.5 643.98,1301.02 665,1280 665,1200 672.56,1192.44 C2.1
NetC2_2: C2.2 X1.4 | length 180
  Bottom Layer w6: X1.4 669.57,1305.43 700,1275 C2.2
NetC7_2: C7.2 X1.25 | length 143.6
  Bottom Layer w6: X1.25 132.17,1334.8 C7.2
NetC10_2: C10.2 X1.26 | length 135.2
  Bottom Layer w6: C10.2 81.97,1300 106.58,1324.61 X1.26
NetC12_1: C12.1 U4.1 X3.1 | length 238
  Bottom Layer w6: C12.1 131.08,520.48 X3.1 166.96,548.04 210.27,504.73 U4.1
NetC13_1: C13.1 U4.2 X3.2 | length 285.3
  Bottom Layer w6: X3.2@95.66,654.34 X3.2 ; C13.1 131.08,681.9 X3.2 ; U4.2 220.58,524.42 103.52,641.48 X3.2
NetC15_2: C15.2 U4.43 | length 76.1
  Bottom Layer w6: U4.43 382.26,430.3 C15.2
NetC16_1: C16.1 D1.2 H1.1 U5.1 U5.2 | length 699.6
  Top Layer w6: v1(720,645) D1.2
  Signal Layer 1 w6: v1@607,294 v1(607,295) 607,352.95 669,414.95 669,499 720,550 v1(720,645)
  Bottom Layer w6: U5.1@545,230 C16.1@545,286.22 ; U5.2 510.31,209.69 505,215 505,225 509.37,229.37 U5.1 ; C16.1@552.68,285.59 C16.1 562.06,294.97 H1.1 H1.1@664.97,294.97
NetC18_1: C18.1 C20.1 S2.2 U6.1 U6.3 | length 425.4
  Bottom Layer w6: S2.2 137.97,260 145,260 140,255 140,215 157.4,197.6 U6.1 242.6,197.6 255,210 255,260.3 242.9,272.4 U6.3 206.97,278.19 C18.1 C20.1
NetC19_1: C19.1 R14.1 U6.5 | length 187.3
  Top Layer w6: v1(310,225) 335,225 346.97,213.03 C19.1
  Bottom Layer w6: R14.1 292.56,162.56 307.24,177.24 U6.5 310,200.35 v1(310,225)
NetD1_3: D1.3 R11.2 | length 130.2
  Top Layer w6: R11.2 685,675 690,670 690,625 703.72,611.28 D1.3
NetD1_4: D1.4 R13.2 | length 97.1
  Top Layer w6: R13.2 690,595 708.88,576.12 D1.4
NetJ1_2: J1.2 U4.13 | length 611.1
  Bottom Layer w6: U4.13 268.22,751.78 250,770 250,935 470.3,1155.3 J1.2
NetJ1_3: J1.3 U4.19 | length 517.5
  Bottom Layer w6: U4.19 401.95,778.05 395,785 380,785 354,811 354,974 491.99,1111.99 J1.3
NetJ1_5: J1.5 U4.20 | length 431.2
  Bottom Layer w6: U4.20 421.63,780.99 401.63,801 389,801 370,820 370,915 480.37,1025.37 J1.5
NetJ1_7: J1.7 U4.21 | length 421.5
  Bottom Layer w6: U4.21 441.32,786.32 460,805 615,805 635,825 635,925 621.24,938.76 J1.7
NetJ1_G4: J1.G4 U4.30 | length 801.8
  Signal Layer 1 w6: v1(376.95,1233.05) 426.95,1233.05 448.85,1211.15 448.85,906.15 555,800 555,675 545,665 545,635 557.16,622.84 v1(567.16,622.84)
  Bottom Layer w6: v1(376.95,1233.05) J1.G4@410,1235 ; U4.30 v1(567.16,622.84)
NetR1_2: R1.2 S1.3 U4.23 | length 830.8
  Top Layer w6: S1.3@499.8,219.8 S1.3 525,194.84 525,180 ; v1(500,180) 525,180 ; R1.2 525,180
  Signal Layer 1 w6: v1(500,180) 500,334.7 470,364.7 470,737 v1(514.69,781.69)
  Bottom Layer w6: U4.23 480.69,775 487.2,781.51 514.51,781.51 v1(514.69,781.69)
NetR2_2: R2.2 S1.2 U4.15 | length 1446.3
  Top Layer w6: S1.2 440,238.03 440,200 v1(475,165) R2.2
  Signal Layer 1 w6: v1(297.69,830) 260,830 130,700 130,350 76,296 76,171.75 105.75,142 411,142 434,165 v1(475,165)
  Bottom Layer w6: v1(297.69,830) 297.69,799.43 323.21,773.91 U4.15
NetR3_2: R3.2 S1.1 U4.14 | length 1395.8
  Top Layer w6: v1(400,310) 412.18,297.82 S1.1 415,290.81 415,200 425,190 R3.2
  Signal Layer 1 w6: v1(275,799.49) 275,760 149,634 149,416 176,389 176,336 109,269 109,184 119,174 373,174 400,201 v1(400,310)
  Bottom Layer w6: v1(275,799.49) 303.52,770.97 U4.14
NetR4_2: R4.2 S1.4 U4.25 | length 910.2
  Top Layer w6: R4.2 675,190 ; 675,175 675,190 ; v1@745,465 v1(744.75,465) S1.4 674.52,394.76 674.52,335.48 715,295 715,230 675,190
  Signal Layer 1 w6: v1(718,727) 738,727 744.75,720.25 v1(744.75,465)
  Bottom Layer w6: U4.25 581.27,721.27 600,740 705,740 v1(718,727)
NetR5_2: R5.2 S1.6 U4.24 | length 772
  Top Layer w6: R5.2 558,134.56 558,388.81 571,401.81 v1(571,474) 598.19,474 S1.6
  Signal Layer 1 w6: v1(517,751) 517,513 556,474 v1(571,474)
  Bottom Layer w6: U4.24 501.15,751 v1(517,751)
NetR6_2: R6.2 X1.24 | length 172.2
  Bottom Layer w6: X1.24@162.48,1410.28 X1.24 157.76,1331.84 168.88,1320.72 196.14,1320.72 216.97,1299.88 R6.2
NetR9_1: R9.1 U4.26 | length 97.5
  Bottom Layer w6: U4.26 R9.1
NetR10_2: R10.2 U5.8 | length 158.5
  Bottom Layer w6: U5.8 435,190 450,175 450,110.59 R10.2
NetR11_1: R11.1 U5.3 | length 680.3
  Top Layer w6: v1(525,475) 525,645 555,675 600,675 R11.1@609.41,665.59
  Signal Layer 1 w6: v1@530,475 v1(525,475) 500.97,450.97 500.97,361.3 520,342.27 520,235 558.69,196.31 v1(600,196.31)
  Bottom Layer w6: U5.3 594.67,190 595.99,191.32 596.32,191.32 600,195 v1(600,196.31)
NetR12_2: R12.2 U5.6 | length 140.8
  Bottom Layer w6: U5.6 391.26,53.74 405,40 R12.2
NetR13_1: R13.1 U5.4 | length 533.7
  Top Layer w6: R13.1 610,594.41 610,570 615,565 v1(615,545)
  Signal Layer 1 w6: v1(604.68,170.32) 630,195.63 630,250 608,272 598.3,272 586,284.3 586,376 619,409 619,445.21 625,451.21 625,535 v1(615,545)
  Bottom Layer w6: U5.4 v1(604.68,170.32)
NetR16_2: R16.2 S3.1 U4.16 | length 1022.6
  Top Layer w6: S3.1 v1(130,195) ; R16.2 S3.1
  Signal Layer 1 w6: v1(130,195) 130,261 192,323 192,398 165,425 165,625 328,788 328,837 v1(315,850)
  Bottom Layer w6: v1(315,850) 320,845 320,799.75 342.89,776.85 U4.16
NetU3_1: U3.1 X2.2 | length 115.9
  Top Layer w6: U3.1 323.59,646.3 X2.2
NetU3_2: U3.2 X2.1 | length 179.3
  Top Layer w6: U3.2 349.18,705.82 375,680 375,650 380,645 X2.1
OLED_RESET: U4.29 X1.12 | length 857.8
  Signal Layer 1 w6: v1(464.85,1315.15) 464.85,915.15 575,805 v1(575,650)
  Bottom Layer w6: v1(464.85,1315.15) X1.12 ; U4.29 552.53,642.53 560,650 v1(575,650)
RESET: H3.10 R15.1 R17.2 S4.2 | length 558
  Top Layer w6: v1(201.97,830) 201.97,685 204.47,682.5 255,682.5 ; R17.2 255,682.5 ; R15.1 255,682.5
  Bottom Layer w6: v1(201.97,830) 201.97,858.03 195.41,864.59 195.41,1000.41 222.44,1027.44 v1(222.44,1140)
SCL: R7.1 U1.6 U2.14 U3.6 U4.32 X1.16 | length 2411.9
  Top Layer w6: U1.6 v1(149.8,845.2) ; v1(170,1045) v1(665,1045) ; U3.6 374.77,890.23 385,880 435,880 449,894 449,954 501,1006 612.83,1006 640.85,977.98 v1(642.02,977.98) U2.14
  Signal Layer 1 w6: v1(149.8,845.2) 149.8,915.2 130,935 130,1005 v1(170,1045) 284,1159 284,1209.73 315.89,1241.63 315.89,1300.59 330.3,1315 370,1315 380,1305 v1(380,1290) ; v1(642.02,977.98) 642.02,779.98 660,762 v1(660,550)
  Bottom Layer w6: X1.16 362.48,1307.52 v1(380,1290) ; U4.32 R7.1 630,561.7 641.7,550 v1(660,550) ; v1(642.02,977.98) 642.02,1022.02 v1(665,1045)
SDA: R8.1 U1.1 U2.13 U3.5 U4.31 X1.17 X1.18 | length 1877.5
  Top Layer w6: U1.1 270.2,845.2 275,850 275,1000 v1(299,1024) 429,1024 ; U3.5 419.65,929.65 429,939 429,1024 ; U2.13 v1(697.14,947.86) 697.14,972.86 646,1024 429,1024
  Signal Layer 1 w6: v1(299,1024) 300,1025 300,1203.11 336.89,1240 v1(336.89,1291.89)
  Bottom Layer w6: X1.18 311.3,1323.7 315,1320 336.89,1320 ; v1(336.89,1291.89) 336.89,1320 ; X1.17 336.89,1320 ; U4.31@532.2,601.84 U4.31 557.14,603.16 558.46,601.84 581.84,601.84 615,635 R8.1 629.41,657.41 639,667 722,667 741,686 741,769 697.14,812.86 v1(697.14,947.86)
SWCLK: H3.4 U4.45 | length 924.1
  Signal Layer 1 w6: v1(331,415) 331,395 319,383 295,383 284,394 284,719 372.44,807.44 v1(372.44,1140)
  Bottom Layer w6: v1(331,415) 331,434 330,435 342.89,447.89 U4.45
SWDIO: H3.2 U4.46 | length 846.7
  Signal Layer 1 w6: v1(305,415) 305,715 419,829 419,874 430,885 430,1132.44 v1(422.44,1140)
  Bottom Layer w6: v1(305,415) 305,435 323.21,453.21 U4.46
TARGET_RESET: R17.1 U4.40 | length 535.7
  Top Layer w6: R17.1 280.12,609.88 300.66,589.34 400.66,589.34 427.14,562.86 427.14,452.86 456.84,423.16 503.16,423.16 v1(525,445)
  Bottom Layer w6: U4.40 441.32,448.68 450,440 520,440 v1(525,445)
pads on no net: H1.4 H3.6 H3.7 H3.8 J1.1 J1.8 S1. S2.3 S3.2 S3.4 U1.3 U1.4 U2.3 U2.8 U2.9 U2.11 U2.12 U3.7 U4.3 U4.4 U4.7 U4.8 U4.9 U4.10 U4.11 U4.12 U4.22 U4.27 U4.28 U4.37 U4.38 U4.39 U4.41 U4.47 U4.48 U5.7 U6.4

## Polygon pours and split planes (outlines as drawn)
GND on Internal Plane 1(GND) (split plane): 756.64,1514.63 761.21,1513.53 765.56,1511.73 769.57,1509.27 773.15,1506.22 776.21,1502.64 778.67,1498.63 780.47,1494.28 781.57,1489.7 781.9,1485.51 781.85,1485.01 781.88,1484.73 781.88,51 781.97,50.01 781.6,45.34 780.51,40.76 778.71,36.41 776.25,32.4 773.19,28.82 769.61,25.76 765.6,23.3 761.25,21.5 756.67,20.4 752.49,20.08 751.98,20.12 751.7,20.1 50.97,20.1 49.98,20 45.31,20.37 40.73,21.47 36.38,23.27 32.37,25.73 28.79,28.78 25.74,32.36 23.28,36.37 21.48,40.72 20.38,45.3 20.03,49.64 20.07,49.99 20.1,49.99 20.07,50.27 20.07,813.65 20.11,814.03 20.01,815.02 20.38,819.69 21.48,824.27 23.28,828.62 25.74,832.63 28.79,836.21 32.37,839.26 36.38,841.72 40.73,843.52 45.31,844.62 49.5,844.95 50,844.9 50.43,844.95 55.61,845.24 61.14,846.18 66.54,847.73 71.73,849.88 76.64,852.6 81.22,855.85 85.41,859.59 89.15,863.78 92.4,868.36 95.12,873.27 97.27,878.46 98.82,883.86 99.76,889.39 100.08,895 100.06,895.25 100.1,895.58 100.1,1194.42 100.06,1194.75 100.08,1195 99.76,1200.61 98.82,1206.14 97.27,1211.54 95.12,1216.73 92.4,1221.64 89.15,1226.22 85.41,1230.41 81.22,1234.15 76.64,1237.4 71.73,1240.12 66.54,1242.27 61.14,1243.82 55.61,1244.76 51.8,1244.98 51,1245.1 50.48,1245.07 49.96,1245.12 49.96,1245.09 49.64,1245.06 45.27,1245.4 40.69,1246.5 36.35,1248.3 32.33,1250.76 28.75,1253.82 25.7,1257.4 23.24,1261.41 21.44,1265.76 20.34,1270.34 19.97,1275.01 20.07,1276 20.07,1484 19.97,1484.99 20.34,1489.66 21.44,1494.24 23.24,1498.59 25.7,1502.6 28.75,1506.18 32.33,1509.24 36.35,1511.7 40.69,1513.5 45.27,1514.6 49.46,1514.92 49.96,1514.88 50.25,1514.9 750.97,1514.9 751.96,1515

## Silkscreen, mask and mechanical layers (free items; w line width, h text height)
Bottom Solder:
  text "Rev1.0" at 775,645 h30 r90
Board Outline:
  the board outline again, w10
